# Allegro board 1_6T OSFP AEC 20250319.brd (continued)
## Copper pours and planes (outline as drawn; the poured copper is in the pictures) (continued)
N17308149 on BOTTOM: 10.01,33.78 10.09,33.7 10.09,33.01 9.98,32.9 7.9,32.9 7.75,33.06 7.75,33.84 7.86,33.95 8.59,33.95 8.76,33.78
N17340476 on TOP: 6.59,18.59 6.59,17.75 5.89,17.04 5.89,16.38 4.16,16.38 4.16,17.08 3.96,17.27 3.46,17.27 3.19,17.55 3.19,18.59
N17341396 on TOP: 14.07,18.59 14.07,17.54 14.56,17.05 14.56,16.38 16.3,16.38 16.3,17.05 16.51,17.26 17.16,17.26 17.46,17.55 17.46,18.59
N17342760 on BOTTOM (solid shape): 15.83,14.06 14.86,14.06 14.84,14.09 14.84,15.15 14.35,15.64 13.84,15.64 13.8,15.68 13.8,15.78 13.83,15.81 14.27,15.81 14.43,15.96 15.83,15.96
N17495631 on BOTTOM: 3.47,27.78 3.47,25.94 3.29,25.76 2.42,25.76 2.39,25.8 2.39,26.92 2.4,26.93 2.4,27.16 2.4,27.16 2.4,27.81 2.42,27.81 2.5,27.9 3.35,27.9
N17495631 on L11_GND: 3.45,30.15 4.01,30.15 4.1,30.06 4.1,28.01 3.23,27.14 2.78,27.14 2.68,27.24 2.68,27.61 3.41,28.34 3.41,30.11
N17552273 on BOTTOM: 8.06,21.23 8.06,21.62 7.93,21.75 7.38,21.75 7.25,21.88 7.25,22.41 7.38,22.54 9.07,22.54 9.31,22.3 9.31,21.26 9.21,21.16 8.13,21.16
N17552308 on BOTTOM: 17.54,27.39 17.54,26.95 17.65,26.84 18.21,26.84 18.35,26.97 18.35,28.83 18.3,28.88 17.23,28.88 17.18,28.83 17.18,27.74
N17587092 on BOTTOM: 4.14,16.44 5.89,16.44 5.89,17.08 6.47,17.66 6.47,18.51 3.09,18.51 3.09,17.67 3.47,17.29 3.96,17.29 4.14,17.11

Small or netless copper shapes (teardrops, artwork), in the pictures only: 148 on TOP, 85 on BOTTOM, 64 on L2_GND, 32 on L4_SIG1, 49 on L9_SIG2, 40 on L11_GND

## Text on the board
Ref Des/Silkscreen Bottom: 30 | - | R8 | + | R7 | R6 | R5 | R4 | R3 | SWCLK | SWDIO | R2 | GND | 3V3 | R1 | 1
Ref Des/Silkscreen Top: 31 | T8 | T7 | T6 | T5 | T4 | T3 | T2 | T1 | 60 | - | + | 5210490 A00 | A1 | TOP
L2_GND: L2_GND
L6_PWR1: L6_PWR1
L7_PWR2: L7_PWR2
L11_GND: L11_GND
COMPVAL_TYPE_TOP: O | + | - | 0.30 mm | 1.0 mm ACROSS PADS | 45 | / | 5 | SCALE_NONE | DETAIL A
User.45: 2.32 REF. | 2.52 REF. | 1.97 REF. | STACKUP BUILDUP | PP | Foil(HVLP) | HVLP3 | Core | PP NAME AND RC | PSR4000 LT02G | PP(1035)RC76 | 1*1035 RC68 | PP(1078)RC67 | (60GHz) | 2.67 | 2.77 | 2.75 | 3.3 | DK | 0.0020 | 0.014 | Df | 1/2 OZ+Plating>=20um | 1 OZ | 2.9 | 2.8 | 5.5 | 3.2 | 3 | N/A | 46 | 4.0/6.6(8.0) | 2.8/7.8(7.9) | L2 | L3 | L3/L5 | L8/L10 | L10 | 93 | 4.0/6.6(8) | TRACE/SPACE | L7/L10 | DIFF2 | (REF) | L5_GND | L3_GND | L4_SIG1 | L9_SIG2 | L11_GND | L6_GND | L8_PWR2 | L10_GND | L10_SIG3 | L8_GND | LAYER 4 SIG1 | LAYER 9 SIG2 | 8 | 13. MODULE FLATNESS OF 0.050 MM AND SURFACE ROUGHNESS OF 0.80 UM. | 14. DRILL FOR 6MIL MUST BE VIA FILL WITH NON-CONDUCTIVE MATERIAL. | 15. PLEASE USE LOW ETCHING BROWN OXIDE. | 12. DRILL FOR  4.5MIL MUST BE VIA FILL WITH COPPER. | 10. FINISH BOARD SHALL MEET THE PERFORMANCE REQUIREMENTS | 11  COPPER THIEVING CAN BE ADDED TO INNER AND OUTER LAYERS. | 2. ENEPIG: 0.05 micrometers minimum gold over, | 3. ALL PLATED HOLES TO HAVE MIN. WALL THICKNESS | 1. MATERIAL: M8U | 9  THIS DESIGN IS VIPPO. VIA-IN-PAD-PLATED-OVER | 8. IT IS THE BOARD MANUFACTURERS RESPONSIBILITY TO MEET | 4. GREEN SOLDER MASK OVER BARE COPPER BOTH SIDES USING | 5. WHITE SILKSCREEN BOTH SIDES WITH NONCONDUCTIVE CONTRASTING | 7. FABRICATE PER DIMENSIONS SHOWN. | 6. BOARD WARPAGE SHALL NOT EXCEED +/-.0075 PER INCH MEASURED | 1.27 micrometers minimum nickel over. | Total board thickness 1.00+/-0.10mm | 0.3 micrometers minimum palladium over, | NOTES: UNLESS OTHERWISE SPECIFIED | THESE HOLE DIAMETER ARE DRILL SIZES NOT FINISHED HOLE SIZES. | SPEED TRACES WITH RACH BOARD LOT SHIPMENT | PROVIDE TDR AND INSERTION LOSS TESTING RESULTS FOR HIGH | 9 | OF .001" COPPER. | ALL HOLE DIAMETERS ARE AFTER PLATING. | IN ACCORDANCE WITH IPC-TM-650, METHOD 2.4.55. | ANY CHANGES NEED TO BE APPROVED. | LASER DIRECT IMAGING SOLDER MASK PER IPC-SM-840. | EPOXY OR INKJET USING ARTWORK SUPPLIED | KEEP MIN DISTANCE OF 100 MILS TO COPPER FEATURE ON ALL LAYERS. | THE IMPEDANCE REQUIREMENTS +/-7%. SUGGESTED DIELECTRIC | DIMENSIONS ARE FOR REFERENCE ONLY. DIELECTRIC REFERENCE | DIMENSIONS REFER TO COPPER SURFACE TO COPPER SURFACE. | OF IPC-6012 CLASS 2. | 12 | 14 | 20.TRACE ONLY IL EVALUATION | 93 OHM L4 1.876  @ 56GHz(REF L3/L5) | 93 OHM L9 1.915  @ 56GHz(REF L8/L10) | 93 OHM L9 1.542  @ 56GHz(REF L7/L10) | 17.WARP AND TWIST OF THE BOARD SHALL NOT EXCEED 0.75% | 18.NOMINAL CONDUCTOR WIDTHS ON FINISHED BOARD TO BE WITHN +/- 15% OR +/- 1MIL, | 19.ANY ALTERATION (INCLUDE VIAS)TO THE DESIGN DATA MUST BE APPROVE BY MARVELL.) | 16. FOR DIMENSION NOT SHOWN,REFER TO THE BOARD OUTLINE DEFINED BY THE CAD DATA. | WJICHEVER IS LESS OF ARTWORK AS DEFINED ON GERBERS AND SUPPLIER APERTURE WIDTHS. | FIGURE | FINISHED_SIZE | 4.5 | 6.0 | TOLERANCE_DRILL | +2.0/-2.0 | DRILL CHART: L9_SIG2 to L10_GND | ALL UNITS ARE IN MILS | DRILL CHART: L10_GND to L11_GND | DRILL CHART: L11_GND to BOTTOM | DRILL CHART: TOP to BOTTOM | PLATED | NONSTANDARD | - | QTY | 1306 | 931 | 999 | 621 | 4.0 | +3.0/-3.0 | DRILL CHART: TOP to L2_GND | DRILL CHART: L5_GND to L6_PWR1 | DRILL CHART: L7_PWR2 to L8_GND | DRILL CHART: L8_GND to L9_SIG2 | DRILL CHART: L2_GND to L3_GND | DRILL CHART: L3_GND to L4_SIG1 | DRILL CHART: L4_SIG1 to L5_GND | DRILL CHART: L4_SIG1 to L9_SIG2 | LASER | 1391 | 172 | 953 | 730 | 1075 | 1281 | 1113 | 263 | P265A033P_A
